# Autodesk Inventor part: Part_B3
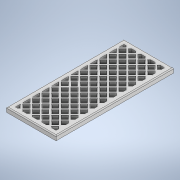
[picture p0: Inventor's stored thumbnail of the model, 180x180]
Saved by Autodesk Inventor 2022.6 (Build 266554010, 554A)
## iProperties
Created: 2025-05
Part Number: Part_B3
Material: Generic
Document SubType Name: Modeling
Designer: khinm
Density: 1 g/cm^3
Appearance: Default
Author: khinm
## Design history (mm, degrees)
sketch "Sketch1"
  geometry: L1 (27.4, -64.9)-(-27.4, -64.9); L2 (-27.4, -64.9)-(-27.4, 64.9); L3 (-27.4, 64.9)-(27.4, 64.9); L4 (27.4, 64.9)-(27.4, -64.9); 3 further points
  constraints: 8 end point, 2 midpoint, 2 parallel, 1 horizontal, 1 horizontal alignment, 1 perpendicular, 1 vertical alignment
  dimensions: "d0" = 54.8 distance of L2.end L3.end; "d1" = 129.8 distance between parallel lines of L3 L1
extrude "Extrusion1" new body sketch "Sketch1" stored distance "d2" = 4.98; taper "d3" = 0 deg
sketch "Sketch2"
  geometry: L1 (22.4, 59.9)-(-22.4, 59.9); L2 (-22.4, -59.9)-(22.4, -59.9); L3 (-27.4, -64.9)-(27.4, -64.9) reference; L4 (-27.4, 64.9)-(-27.4, -64.9) reference; L5 (-18.964, 58.336)-(-22.4, 54.9); L6 (21.899, -59.9)-(22.4, -59.399); L7 (21.899, 59.9)-(22.4, 59.399); L8 (-18.964, -58.336)-(-22.4, -54.9); L9 (16.392, 58.336)-(19.927, 54.801); L10 (21.695, 53.033)-(22.4, 52.328); L11 (19.927, 51.265)-(22.4, 48.792); L12 (22.4, 53.738)-(21.695, 53.033); L13 (17.955, 59.9)-(16.392, 58.336); L14 (11.292, 59.9)-(12.856, 58.336); L15 (14.624, 56.569)-(18.159, 53.033); L16 (12.856, 58.336)-(9.321, 54.801); L17 (5.785, 58.336)-(9.321, 54.801); L18 (14.624, 56.569)-(11.088, 53.033); L19 (11.088, 53.033)-(14.624, 49.497); L20 (9.321, 51.265)-(12.856, 47.73); L21 (19.927, 51.265)-(16.392, 47.73); L22 (16.392, 47.73)-(19.927, 44.194); L23 (21.695, 42.426)-(22.4, 41.721); L24 (14.624, 45.962)-(18.159, 42.426); L25 (19.927, 40.659)-(22.4, 38.186); L26 (22.4, 46.667)-(19.927, 44.194); L27 (22.4, 43.131)-(21.695, 42.426); L28 (19.927, 40.659)-(16.392, 37.123); L29 (18.159, 42.426)-(14.624, 38.891); L30 (14.624, 45.962)-(11.088, 42.426); L31 (11.088, 42.426)-(14.624, 38.891); L32 (12.856, 37.123)-(9.321, 40.659); L33 (12.856, 47.73)-(9.321, 44.194); L34 (5.785, 47.73)-(9.321, 44.194); L35 (9.321, 51.265)-(5.785, 47.73); L36 (7.553, 42.426)-(4.017, 45.962); L37 (7.553, 53.033)-(4.017, 49.497); L38 (16.392, 37.123)-(19.927, 33.588); L39 (21.695, 31.82)-(22.4, 31.115); L40 (22.4, 27.579)-(19.927, 30.052); L41 (18.159, 31.82)-(14.624, 35.355); L42 (22.4, 32.525)-(21.695, 31.82); L43 (22.4, 36.06)-(19.927, 33.588); L44 (22.4, 20.508)-(21.695, 21.213); L45 (22.4, 16.973)-(19.927, 19.445); L46 (22.4, 21.918)-(21.695, 21.213); L47 (22.4, 25.454)-(19.927, 22.981); L48 (19.927, 30.052)-(16.392, 26.517); L49 (19.927, 22.981)-(16.392, 26.517); L50 (18.159, 21.213)-(14.624, 24.749); L51 (18.159, 31.82)-(14.624, 28.284); L52 (14.624, 35.355)-(11.088, 31.82); L53 (12.856, 37.123)-(9.321, 33.588); L54 (9.321, 40.659)-(5.785, 37.123); L55 (7.553, 42.426)-(4.017, 38.891); L56 (14.624, 28.284)-(11.088, 31.82); L57 (12.856, 26.517)-(9.321, 30.052); L58 (9.321, 22.981)-(5.785, 26.517); L59 (7.553, 21.213)-(4.017, 24.749); L60 (14.624, 17.678)-(11.088, 21.213); L61 (12.856, 15.91)-(9.321, 19.445); L62 (9.321, 12.374)-(5.785, 15.91); L63 (7.553, 10.607)-(4.017, 14.142); L64 (22.4, 9.902)-(21.695, 10.607)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; 49 further points
  constraints: 1503 parallel, 834 end point, 11 point on line, 2 horizontal, 1 horizontal alignment, 1 midpoint, 1 vertical alignment, 45 other
  dimensions: "d4" = 5 distance between parallel lines of L3 L2; "d5" = 5 dimension on L4; "d6" = 5 distance of L5.end L1.end; "d44" = 1.87262 distance of L1.end L78.end
extrude "Extrusion2" cut sketch "Sketch2" stored distance "d45" = 3.48; taper "d46" = 0 deg
chamfer "Chamfer1" distance "d47" = 0.4; stored, may be unused: second distance "d48" = 2, angle "d49" = 45 deg
fillet "Fillet1" dims "d50" = 1
body "Solid1"
other parameters: "d4" = 5, "d5" = 5, "d6" = 5, "d8" = 2.5, "d9" = 5, "d10" = 2.5, "d11" = 5, "d12" = 2.5, "d13" = 5, "d14" = 2.5, "d15" = 5, "d16" = 2.5, "d17" = 5, "d18" = 2.5, "d19" = 5, "d20" = 2.5, "d21" = 5, "d22" = 2.5, "d23" = 5, "d24" = 2.5, "d25" = 5, "d26" = 2.5, "d27" = 5, "d28" = 2.5, "d29" = 5, "d30" = 2.5, "d32" = 2.5, "d33" = 5, "d34" = 2.5, "d35" = 5, "d36" = 2.5, "d37" = 5, "d38" = 5, "d39" = 5, "d40" = 5, "d41" = 2.5, "d42" = 2.5, "d43" = 5, "d44" = 1.87262
